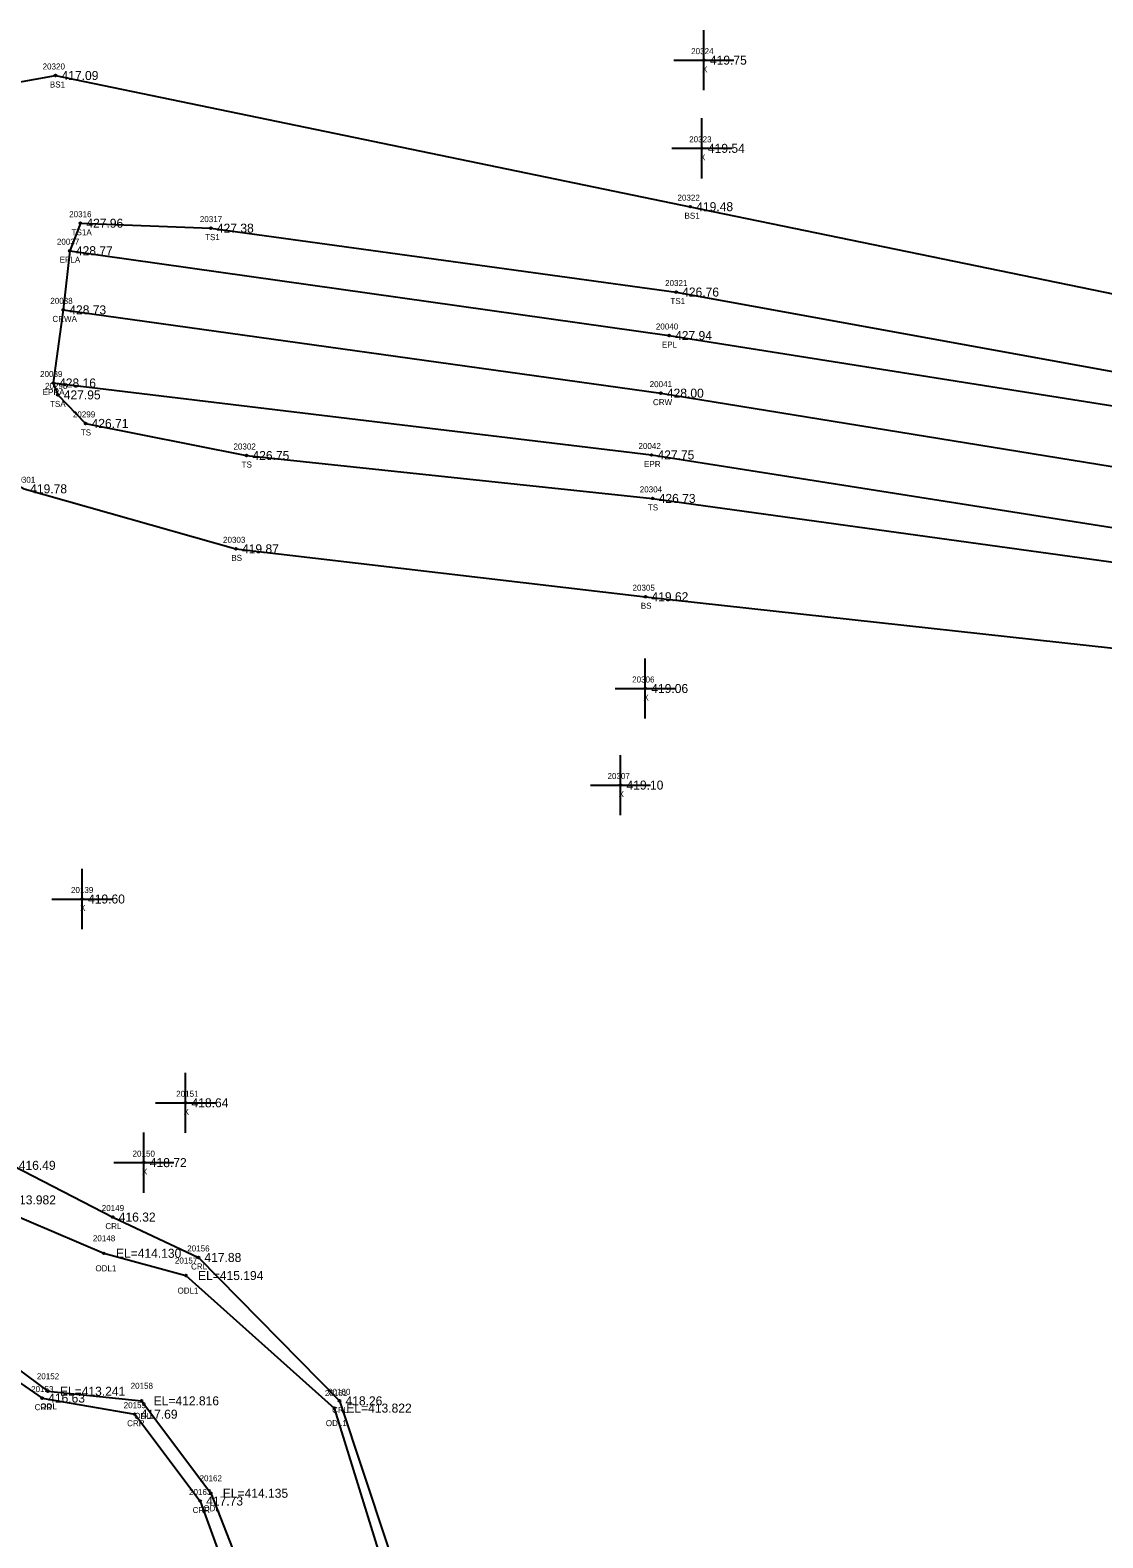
# Model space of a CAD drawing. Extents: x 1613184 to 1614731, y 770859 to 771868.
# Drawn here: x 1613959.6 to 1614138.1, y 771132.5 to 771383.4 of the extents above; entities that cross this region are included whole.
import ezdxf

# ---------------------------------------------------------------- set-up
doc = ezdxf.new("R2010")
doc.units = 0
for name, color, linetype in [('RD_DTM_BkLn1', 7, 'Continuous'), ('RD_DTM_BkLn2', 7, 'Continuous'), ('RD_DTM_BkLn_txCode', 7, 'Continuous'), ('RD_EX_H2O', 7, 'Continuous'), ('RD_EX_H2O_txCode', 7, 'Continuous'), ('RD_EX_Misc', 7, 'Continuous'), ('RD_EX_Misc_txCode', 7, 'Continuous'), ('RD_EX_Road', 7, 'Continuous'), ('RD_EX_Road_txCode', 7, 'Continuous'), ('RD_EX_TX_H2O_ELEV', 7, 'Continuous'), ('RD_EX_TX_Misc_ELEV', 7, 'Continuous'), ('RD_EX_TX_Road_ELEV', 7, 'Continuous'), ('RD_HC_Survey_ELEV', 7, 'Continuous'), ('RD_HC_Survey_txCode', 7, 'Continuous'), ('RD_SMD_Locator', 7, 'Continuous')]:
    doc.layers.add(name, color=color, linetype=linetype)

msp = doc.modelspace()

# ---------------------------------------------------------------- linework, layer by layer
at = {"layer": 'RD_DTM_BkLn1'}
msp.add_lwpolyline([(1613965.11, 771336.88), (1614064.55, 771323.02), (1614163.88, 771306.86), (1614262.51, 771291.89), (1614361.57, 771275.2), (1614461.76, 771258.77), (1614560.71, 771243.49), (1614660.13, 771228.22)], dxfattribs=at)
at = {"layer": 'RD_DTM_BkLn2'}
for points in [[(1613936.71, 771369.76), (1613950.83, 771373.56), (1613963.82, 771375.88), (1614069.43, 771354.05), (1614168.59, 771333.61), (1614242.69, 771319.53), (1614249.02, 771318.73)], [(1613967.95, 771351.3), (1613966.21, 771346.72), (1613965.11, 771336.88), (1613963.41, 771324.71), (1613964.19, 771322.73)], [(1613967.95, 771351.3), (1613989.67, 771350.48), (1614067.09, 771339.84), (1614166.9, 771321.7), (1614241.35, 771310.16), (1614249.01, 771310.92), (1614252.45, 771315.33), (1614253.58, 771323.09), (1614240.02, 771322.23)], [(1613964.19, 771322.73), (1613968.82, 771317.98), (1613995.59, 771312.64), (1614063.18, 771305.5), (1614161.48, 771291.91), (1614259.01, 771275.6), (1614358.23, 771261.08), (1614459.56, 771246.25), (1614559.08, 771230.48), (1614643.28, 771216.31), (1614658.67, 771214.41)], [(1613942.37, 771316.04), (1613958.6, 771307.1), (1613993.85, 771297.11), (1614061.98, 771289.14), (1614161.12, 771278.24), (1614255.97, 771263.05), (1614304.44, 771258.76), (1614327.58, 771260.25), (1614357.86, 771257.94), (1614459.3, 771244.57), (1614558.63, 771228.44), (1614632.25, 771215.15), (1614636.04, 771209.87), (1614639.16, 771208.8), (1614642.36, 771211.01), (1614643.75, 771203.68), (1614650.35, 771198.32), (1614658.52, 771198.65)]]:
    msp.add_lwpolyline(points, dxfattribs=at)
at = {"layer": 'RD_EX_H2O'}
for points in [[(1613914.71, 771327.05), (1613912.94, 771270.2), (1613909.29, 771229.14), (1613936.32, 771173.24), (1613961.59, 771155.78), (1613976.99, 771153.11), (1613987.89, 771138.66), (1614016.07, 771061.15), (1614064.07, 770971.34), (1614114.62, 770881.02)], [(1613918.3, 771327.47), (1613915.56, 771269.65), (1613912.54, 771229.9), (1613937.35, 771175.56), (1613962.55, 771156.92), (1613978.15, 771155.33), (1613989.65, 771139.95), (1614019.92, 771062.64), (1614066.64, 770972.38), (1614116.22, 770882.03)], [(1613939.34, 771325.64), (1613936.19, 771267.33), (1613931.54, 771235.48), (1613951.01, 771188.77), (1613971.87, 771179.88), (1613985.53, 771176.18), (1614010.21, 771154.12), (1614036.29, 771069.78), (1614094.78, 770976.9), (1614137.18, 770892.4)], [(1613940.63, 771325.49), (1613938.42, 771267.33), (1613934.3, 771235.92), (1613956.7, 771194.52), (1613973.34, 771185.91), (1613987.6, 771179.19), (1614011.07, 771155.33), (1614038.76, 771071.93), (1614097.41, 770977.46), (1614139.24, 770893.98)]]:
    msp.add_lwpolyline(points, dxfattribs=at)
at = {"layer": 'RD_EX_Misc'}
for p, q in [((1614071.71, 771373.43), (1614071.71, 771383.43)), ((1614066.71, 771378.43), (1614076.71, 771378.43)), ((1614071.38, 771358.76), (1614071.38, 771368.76)), ((1614066.38, 771363.76), (1614076.38, 771363.76)), ((1614061.95, 771268.87), (1614061.95, 771278.87)), ((1614056.95, 771273.87), (1614066.95, 771273.87)), ((1614057.83, 771252.8), (1614057.83, 771262.8)), ((1614052.83, 771257.8), (1614062.83, 771257.8)), ((1613968.23, 771233.84), (1613968.23, 771243.84)), ((1613963.23, 771238.84), (1613973.23, 771238.84)), ((1613985.45, 771199.92), (1613985.45, 771209.92)), ((1613980.45, 771204.92), (1613990.45, 771204.92)), ((1613978.51, 771189.97), (1613978.51, 771199.97)), ((1613973.51, 771194.97), (1613983.51, 771194.97))]:
    msp.add_line(p, q, dxfattribs=at)
at = {"layer": 'RD_EX_Road'}
for points in [[(1613966.21, 771346.72), (1614065.91, 771332.61), (1614166, 771316.74), (1614252.8, 771303.53), (1614264.27, 771301.76), (1614271.95, 771300.8), (1614363.43, 771285.99), (1614463.49, 771269.68), (1614562.24, 771253.72), (1614661.91, 771238.32)], [(1613963.41, 771324.71), (1614062.98, 771312.73), (1614162.48, 771297.04), (1614260.87, 771281.9), (1614360.23, 771265.95), (1614460.24, 771249.77), (1614559.17, 771233.87), (1614658.84, 771218.34)]]:
    msp.add_lwpolyline(points, dxfattribs=at)
at = {"layer": 'RD_SMD_Locator'}
for centre in [(1614071.71, 771378.43), (1613963.82, 771375.88), (1614071.38, 771363.76), (1614069.43, 771354.05), (1613967.95, 771351.3), (1613989.67, 771350.48), (1613966.21, 771346.72), (1614067.09, 771339.84), (1613965.11, 771336.88), (1614065.91, 771332.61), (1613963.41, 771324.71), (1613964.19, 771322.73), (1614064.55, 771323.02), (1613968.82, 771317.98), (1613995.59, 771312.64), (1614062.98, 771312.73), (1614063.18, 771305.5), (1613993.85, 771297.11), (1614061.98, 771289.14), (1614061.95, 771273.87), (1614057.83, 771257.8), (1613968.23, 771238.84), (1613985.45, 771204.92), (1613978.51, 771194.97), (1613973.34, 771185.91), (1613971.87, 771179.88), (1613987.6, 771179.19), (1613985.53, 771176.18), (1613962.55, 771156.92), (1613961.59, 771155.78), (1613978.15, 771155.33), (1614010.21, 771154.12), (1614011.07, 771155.33), (1613976.99, 771153.11), (1613987.89, 771138.66), (1613989.65, 771139.95)]:
    msp.add_circle(centre, 0.15, dxfattribs=at)

# ---------------------------------------------------------------- texts
at = {"layer": 'RD_DTM_BkLn_txCode'}
for s, p in [('20320', (1613961.67, 771376.88)), ('BS1', (1613962.88, 771373.88)), ('20322', (1614067.31, 771355.05)), ('20316', (1613966.09, 771352.3)), ('20317', (1613987.83, 771351.48)), ('BS1', (1614068.48, 771352.05)), ('TS1A', (1613966.5, 771349.3)), ('TS1', (1613988.71, 771348.48)), ('20321', (1614065.25, 771340.84)), ('TS1', (1614066.13, 771337.84)), ('20298', (1613962.07, 771323.73)), ('TSA', (1613962.9, 771320.73)), ('20299', (1613966.71, 771318.98)), ('TS', (1613968.03, 771315.98)), ('20302', (1613993.43, 771313.64)), ('TS', (1613994.79, 771310.64)), ('20301', (1613956.73, 771308.1)), ('20304', (1614061.03, 771306.5)), ('TS', (1614062.39, 771303.5)), ('20303', (1613991.69, 771298.11)), ('BS', (1613993.07, 771295.11)), ('20305', (1614059.83, 771290.14)), ('BS', (1614061.21, 771287.14))]:
    msp.add_text(s, height=1, dxfattribs=at).set_placement(p)
at = {"layer": 'RD_EX_H2O_txCode'}
for s, p in [('20149', (1613971.51, 771186.91)), ('CRL', (1613972.11, 771183.91)), ('20148', (1613970.04, 771181.88)), ('20157', (1613983.69, 771178.18)), ('20156', (1613985.74, 771180.19)), ('ODL1', (1613970.46, 771176.88)), ('CRL', (1613986.37, 771177.19)), ('ODL1', (1613984.12, 771173.18)), ('20152', (1613960.71, 771158.92)), ('20153', (1613959.76, 771156.78)), ('20158', (1613976.32, 771157.33)), ('20161', (1614008.64, 771156.12)), ('20160', (1614009.17, 771156.33)), ('CRR', (1613960.34, 771153.78)), ('ODL', (1613961.3, 771153.92)), ('20159', (1613975.16, 771154.11)), ('CRL', (1614009.84, 771153.33)), ('CRR', (1613975.74, 771151.11)), ('ODL', (1613976.91, 771152.33)), ('ODL1', (1614008.8, 771151.12)), ('20162', (1613987.79, 771141.95)), ('20163', (1613986.03, 771139.66)), ('CRR', (1613986.63, 771136.66)), ('ODL', (1613988.41, 771136.95))]:
    msp.add_text(s, height=1, dxfattribs=at).set_placement(p)
at = {"layer": 'RD_EX_Misc_txCode'}
for s, p in [('20324', (1614069.59, 771379.43)), ('X', (1614071.4, 771376.43)), ('20323', (1614069.26, 771364.76)), ('X', (1614071.07, 771361.76)), ('20306', (1614059.77, 771274.87)), ('X', (1614061.64, 771271.87)), ('20307', (1614055.67, 771258.8)), ('X', (1614057.51, 771255.8)), ('20139', (1613966.39, 771239.84)), ('X', (1613967.91, 771236.84)), ('20151', (1613983.9, 771205.92)), ('X', (1613985.14, 771202.92)), ('20150', (1613976.64, 771195.97)), ('X', (1613978.2, 771192.97))]:
    msp.add_text(s, height=1, dxfattribs=at).set_placement(p)
at = {"layer": 'RD_EX_Road_txCode'}
for s, p in [('20037', (1613964.05, 771347.72)), ('EPLA', (1613964.51, 771344.72)), ('20040', (1614063.72, 771333.61)), ('EPL', (1614064.71, 771330.61)), ('20039', (1613961.25, 771325.71)), ('EPRA', (1613961.69, 771322.71)), ('20042', (1614060.82, 771313.73)), ('EPR', (1614061.75, 771310.73))]:
    msp.add_text(s, height=1, dxfattribs=at).set_placement(p)
at = {"layer": 'RD_EX_TX_H2O_ELEV'}
for s, p in [('416.49', (1613957.7, 771193.77)), ('EL=413.982', (1613953.01, 771188.02)), ('416.32', (1613974.34, 771185.16)), ('EL=414.130', (1613973.87, 771179.13)), ('417.88', (1613988.6, 771178.44)), ('EL=415.194', (1613987.53, 771175.43)), ('416.63', (1613962.59, 771155.03)), ('EL=413.241', (1613964.55, 771156.17)), ('417.69', (1613977.99, 771152.36)), ('EL=412.816', (1613980.15, 771154.58)), ('418.26', (1614012.07, 771154.58)), ('EL=413.822', (1614012.21, 771153.37)), ('417.73', (1613988.89, 771137.91)), ('EL=414.135', (1613991.65, 771139.2))]:
    msp.add_text(s, height=1.5, dxfattribs=at).set_placement(p)
at = {"layer": 'RD_EX_TX_Misc_ELEV'}
for s, p in [('419.75', (1614072.71, 771377.68)), ('417.09', (1613964.82, 771375.13)), ('419.54', (1614072.38, 771363.01)), ('419.48', (1614070.43, 771353.3)), ('427.96', (1613968.95, 771350.55)), ('427.38', (1613990.67, 771349.73)), ('426.76', (1614068.09, 771339.09)), ('427.95', (1613965.19, 771321.98)), ('426.71', (1613969.82, 771317.23)), ('426.75', (1613996.59, 771311.89)), ('419.78', (1613959.6, 771306.35)), ('426.73', (1614064.18, 771304.75)), ('419.87', (1613994.85, 771296.36)), ('419.62', (1614062.98, 771288.39)), ('419.06', (1614062.95, 771273.12)), ('419.10', (1614058.83, 771257.05)), ('419.60', (1613969.23, 771238.09)), ('418.64', (1613986.45, 771204.17)), ('418.72', (1613979.51, 771194.22))]:
    msp.add_text(s, height=1.5, dxfattribs=at).set_placement(p)
at = {"layer": 'RD_EX_TX_Road_ELEV'}
for s, p in [('428.77', (1613967.21, 771345.97)), ('427.94', (1614066.91, 771331.86)), ('428.16', (1613964.41, 771323.96)), ('427.75', (1614063.98, 771311.98))]:
    msp.add_text(s, height=1.5, dxfattribs=at).set_placement(p)
at = {"layer": 'RD_HC_Survey_ELEV'}
for s, p in [('428.73', (1613966.11, 771336.13)), ('428.00', (1614065.55, 771322.27))]:
    msp.add_text(s, height=1.5, dxfattribs=at).set_placement(p)
at = {"layer": 'RD_HC_Survey_txCode'}
for s, p in [('20038', (1613962.95, 771337.88)), ('CRWA', (1613963.3, 771334.88)), ('20041', (1614062.68, 771324.02)), ('CRW', (1614063.23, 771321.02))]:
    msp.add_text(s, height=1, dxfattribs=at).set_placement(p)

doc.saveas('drawing.dxf')
